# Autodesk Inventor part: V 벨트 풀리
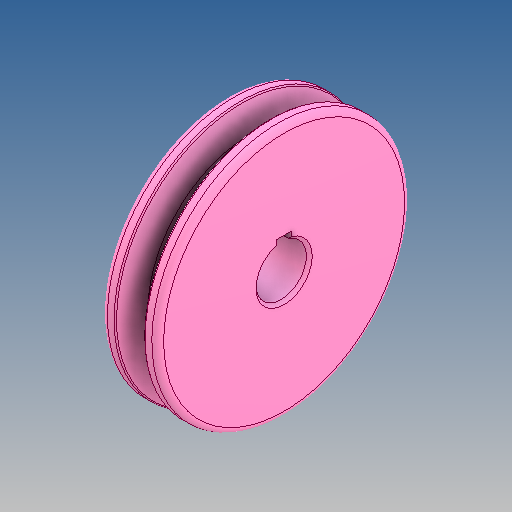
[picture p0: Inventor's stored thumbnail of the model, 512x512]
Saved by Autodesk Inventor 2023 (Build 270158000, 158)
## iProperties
Created: 2025-03
Part Number: V 벨트 풀리
Material: 알루미늄 6061
Document SubType Name: Modeling
Designer: Admin
Density: 2.71 g/cm^3
Appearance: 기본값
Author: jhkim
Sending System: Autodesk Inventor 2025
Preprocessor: ST-DEVELOPER v20
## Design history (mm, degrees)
node "V 벨트 풀리1"
node "솔리드2"
node "솔리드1"
